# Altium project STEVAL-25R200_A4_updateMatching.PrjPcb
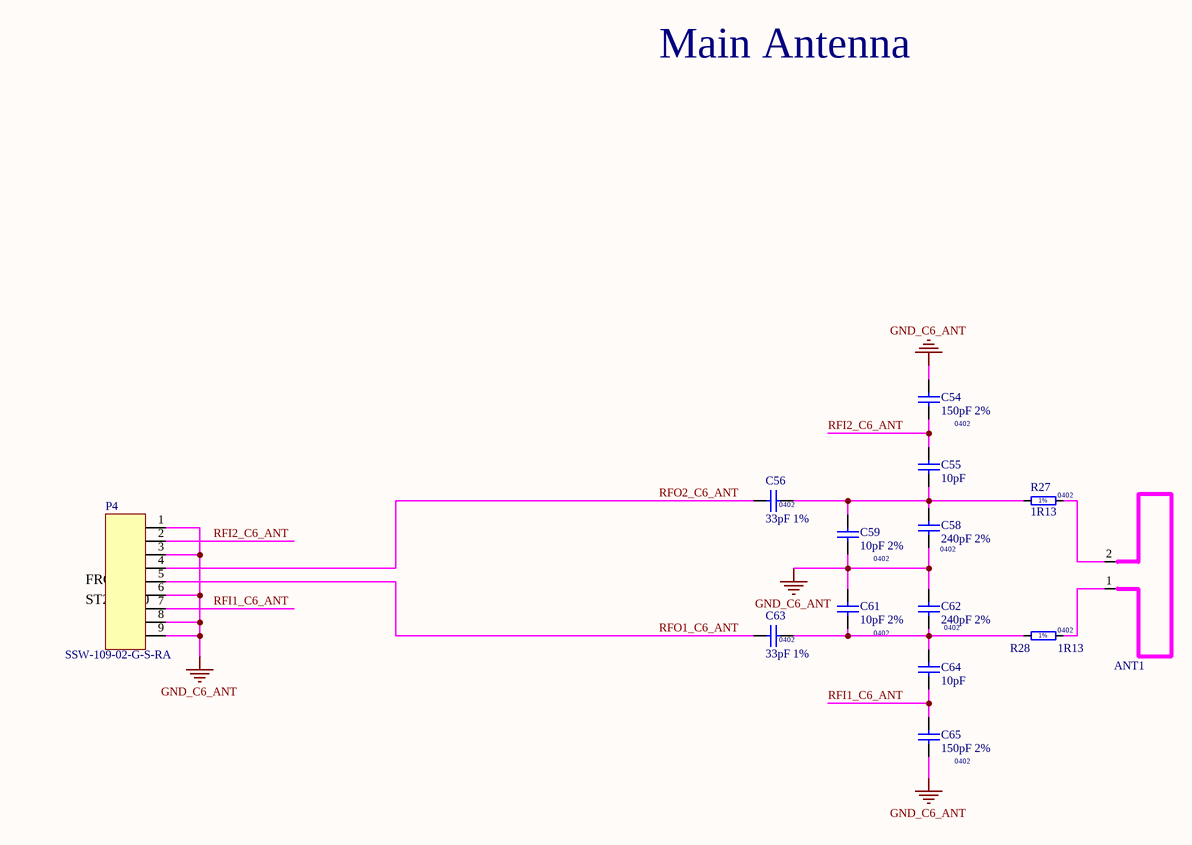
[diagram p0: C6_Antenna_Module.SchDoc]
Company: ST MICROELECTRONICS; date_Dossier: 20 JUNE 2023; Entete_Fichiers_Output: STEVAL-25R200_A2; Reference: /; Revision: A2; Schematics_Reference: /; Schematics_Revision: A2; Schematics_Title: STEVAL-25R200; text_ident_couches: STEVAL-25R200 REV. A2; Title: STEVAL-25R200; Titre_BOM: STEVAL-25R200
7 sheets, 269 parts. Net scope: flat (ports and power ports of the same name join across sheets).
Board file: STEVAL-25R200_A2.PcbDoc
Sheets:
  C6_Antenna_Module.SchDoc
  ST25R200_Module.SchDoc
  STLink_V2.SchDoc
  Hub_And_C7_Antennas.SchDoc
  50_Ohms_Interface.SchDoc
  Flex_Antenna.SchDoc
  Tags.SchDoc

## Sheet C6_Antenna_Module.SchDoc: STEVAL-25R200
size A3; Organization: STMicroelectronics; Address1: SMD Division; Address2: 190, avenue Célestin COQ; Address3: 13106 ROUSSET Cedex; Address4: FRANCE; Revision: A2; SheetNumber: 3; SheetTotal: 7; PageSetup: Record=PageOptions¦CenterHorizontal=True¦CenterVertical=True¦PrintScale=0.71¦XCorrection=1.00¦YCorrection=1.00¦PrintKind=0¦BorderSize=5000000¦LeftOffset=0¦BottomOffset=0¦Orientation=2¦PaperLength=1000¦PaperWidth=1000¦Scale=100¦PaperSource=7¦PrintQuality=-4¦MediaType=1¦DitherType=10¦PaperKind=A4¦PrintScaleMode=1; Reference: /

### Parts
ANT1  ANTENNA-HW-R+T  [ANTENNA-HWR+T]  (value not drawn)  (net tie, no BOM)
C54  150pF 2%  [0402]
C55  10pF  [0402]
C56  33pF 1%  [0402]
C58  240pF 2%  [0402]
C59  10pF 2%  [0402]
C61  10pF 2%  [0402]
C62  240pF 2%  [0402]
C63  33pF 1%  [0402]
C64  10pF  [0402]
C65  150pF 2%  [0402]
P4  SSW-109-02-G-S-RA  [SAMTEC-SSW-1X9PTS-RA-THROUGH-HOLE]
R27  1R13  [0402]
R28  1R13  [0402]

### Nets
GND_C6_ANT: C54.2 C58.1 C59.1 C61.2 C62.2 C65.1 P4.1 P4.3 P4.6 P4.8 P4.9
RFI1_C6_ANT: C64.1 C65.2 P4.7
RFI2_C6_ANT: C54.1 C55.2 P4.2
RFO1_C6_ANT: C63.1 P4.5
RFO2_C6_ANT: C56.1 P4.4
NetANT1_1: ANT1.1 R28.2
NetANT1_2: ANT1.2 R27.2
NetC55_1: C55.1 C56.2 C58.2 C59.2 R27.1
NetC61_1: C61.1 C62.1 C63.2 C64.2 R28.1

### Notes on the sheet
- Main Antenna
- FROM
- ST25R200

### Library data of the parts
ANT1 = ANTENNA-HW-R+T: ANTENNA FOR HW R+T PROJECT; PickPlace: No
C54 C65 = Capacitor 0402 150pF 50V 2% COG: Manufacturer: MULTI-SOURCES; PickPlace: Yes
C55 = Capacitor 0402 10pF 25V 5% NPO: Capacitor 0402 10pF 50V 2% C0G; Manufacturer: MURATA; Manufacturer Part Number: GCM1555C1H100GA16J; PickPlace: Yes
C56 C63 = Capacitor 0402 36pF 50V 2% COG: Capacitor 0402 33pF 50V 1% COG; Manufacturer: MURATA; Manufacturer Part Number: GCM1555C1H330FA16J; PickPlace: Yes
C58 C62 = Capacitor 0402 240pF 50V 2% COG: Manufacturer: MULTI-SOURCES; PickPlace: Yes
C59 = Capacitor 0402 22pF 50V 2% COG: Capacitor 0402 10pF 50V 2% COG; Manufacturer: MURATA; Manufacturer Part Number: GCM1555C1H100GA16J; PickPlace: Yes
C61 = Capacitor 0402 22pF 50V 2% COG: Manufacturer: MURATA; Manufacturer Part Number: GCM1555C1H100GA16J; PickPlace: Yes
C64 = Capacitor 0402 10pF 25V 5% NPO: Capacitor 0402 10pF 50V 2% C0G; Manufacturer: MULTI-SOURCES; PickPlace: Yes
P4 = SSW-109-02-G-S-RA: CONNECTOR SSW-109-02-G-S-RA; Manufacturer: SAMTEC; PickPlace: No
R27 R28 = Resistor 0402 1R13 1%: RESISTOR 0402 1.13 Ohm 1%; Manufacturer: MULTI-SOURCES; PickPlace: Yes

## Sheet ST25R200_Module.SchDoc: STEVAL-25R200
size A3; Organization: STMicroelectronics; Address1: SMD Division; Address2: 190, avenue Célestin COQ; Address3: 13106 ROUSSET Cedex; Address4: FRANCE; Revision: A2; SheetNumber: 2; SheetTotal: 7; PageSetup: Record=PageOptions¦CenterHorizontal=True¦CenterVertical=True¦PrintScale=0.71¦XCorrection=1.00¦YCorrection=1.00¦PrintKind=0¦BorderSize=5000000¦LeftOffset=0¦BottomOffset=0¦Orientation=2¦PaperLength=1000¦PaperWidth=1000¦Scale=100¦PaperSource=7¦PrintQuality=-4¦MediaType=1¦DitherType=10¦PaperKind=A4¦PrintScaleMode=1; Reference: /
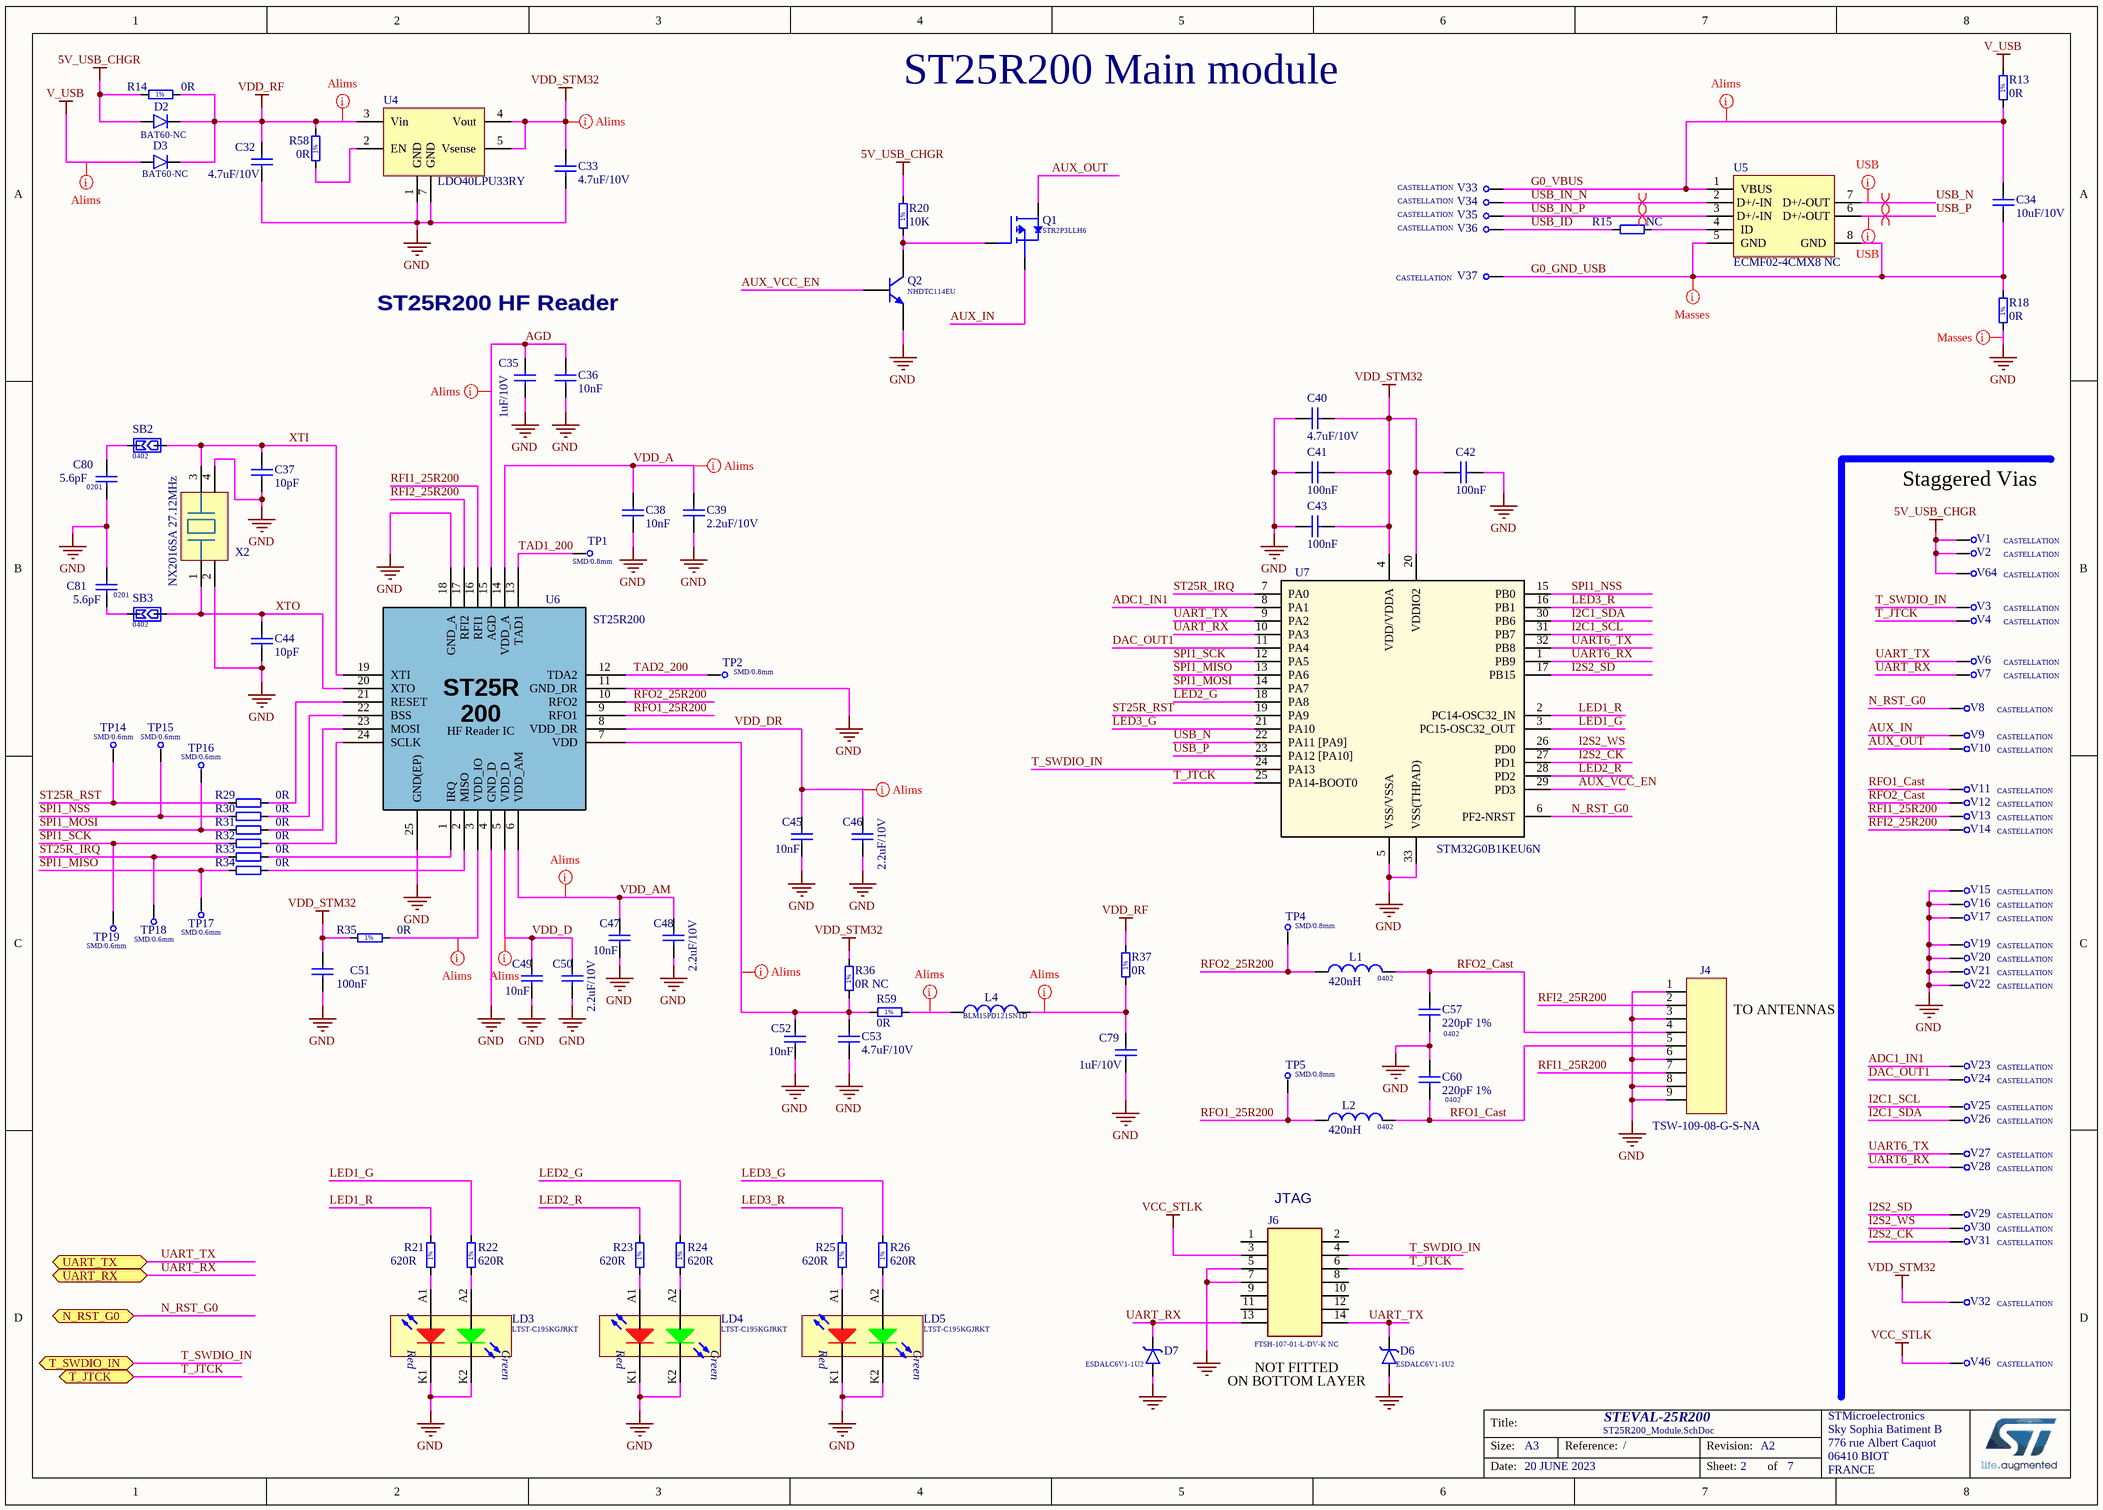
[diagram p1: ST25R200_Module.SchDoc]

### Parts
C32  4.7uF/10V  [0402]
C33  4.7uF/10V  [0402]
C34  10uF/10V  [0402]
C35  1uF/10V  [0201-CAP]
C36  10nF  [0201-CAP]
C37  10pF  [0201-CAP]
C38  10nF  [0201-CAP]
C39  2.2uF/10V  [0201-CAP]
C40  4.7uF/10V  [0402]
C41  100nF  [0201-CAP]
C42  100nF  [0201-CAP]
C43  100nF  [0201-CAP]
C44  10pF  [0201-CAP]
C45  10nF  [0201-CAP]
C46  2.2uF/10V  [0201-CAP]
C47  10nF  [0201-CAP]
C48  2.2uF/10V  [0201-CAP]
C49  10nF  [0201-CAP]
C50  2.2uF/10V  [0201-CAP]
C51  100nF  [0201-CAP]
C52  10nF  [0201-CAP]
C53  4.7uF/10V  [0402]
C57  220pF 1%  [0402]
C60  220pF 1%  [0402]
C79  1uF/10V  [0201-CAP]
C80  5.6pF  Package: 0201  [0201-CAP]
C81  5.6pF  Package: 0201  [0201-CAP]
D2  BAT60-NC  [SOD323]
D3  BAT60-NC  [SOD323]
D6  ESDALC6V1-1U2  [ST-ST0201]
D7  ESDALC6V1-1U2  [ST-ST0201]
J4  TSW-109-08-G-S-NA  [SAMTEC-TSW-1X9PTS-NA-STYLE-08]
J6  FTSH-107-01-L-DV-K NC  [SAMTEC-FTSH-107-01-X-DV-K]
L1  420nH  Package: 0402  [COILCRAFT-SELF-SERIE-0402DF]
L2  420nH  Package: 0402  [COILCRAFT-SELF-SERIE-0402DF]
L4  BLM15PD121SN1D  [0402-SELF]
LD3  LTST-C195KGJRKT  [LITE-ON-SMD-CHIP-LED-TOP-VIEW-BICOLOR-0606]
LD4  LTST-C195KGJRKT  [LITE-ON-SMD-CHIP-LED-TOP-VIEW-BICOLOR-0606]
LD5  LTST-C195KGJRKT  [LITE-ON-SMD-CHIP-LED-TOP-VIEW-BICOLOR-0606]
Q1  STR2P3LLH6  [SOT23-G-D-S]
Q2  NHDTC114EU  [SOT323-BCE]
R13  0R  [0402]
R14  0R  [0402]
R15  NC  [0201-RES]
R18  0R  [0402]
R20  10K  [0402]
R21  620R  [0402]
R22  620R  [0402]
R23  620R  [0402]
R24  620R  [0402]
R25  620R  [0402]
R26  620R  [0402]
R29  0R  [0201-RES]
R30  0R  [0201-RES]
R31  0R  [0201-RES]
R32  0R  [0201-RES]
R33  0R  [0201-RES]
R34  0R  [0201-RES]
R35  0R  [0402]
R36  0R NC  [0402]
R37  0R  [0402]
R58  0R  [0402]
R59  0R  [0402]
SB2  0402  [STRAP-FORMAT-0402-OUVERT]
SB3  0402  [STRAP-FORMAT-0402-OUVERT]
TP1  SMD/0.8mm  [PLAGE-CMS-DIAM-0.8mm]  (no BOM)
TP2  SMD/0.8mm  [PLAGE-CMS-DIAM-0.8mm]  (no BOM)
TP4  SMD/0.8mm  [PLAGE-CMS-DIAM-0.8mm]  (no BOM)
TP5  SMD/0.8mm  [PLAGE-CMS-DIAM-0.8mm]  (no BOM)
TP14  SMD/0.6mm  [PLAGE-CMS-DIAM-0.6mm]  (no BOM)
TP15  SMD/0.6mm  [PLAGE-CMS-DIAM-0.6mm]  (no BOM)
TP16  SMD/0.6mm  [PLAGE-CMS-DIAM-0.6mm]  (no BOM)
TP17  SMD/0.6mm  [PLAGE-CMS-DIAM-0.6mm]  (no BOM)
TP18  SMD/0.6mm  [PLAGE-CMS-DIAM-0.6mm]  (no BOM)
TP19  SMD/0.6mm  [PLAGE-CMS-DIAM-0.6mm]  (no BOM)
U4  LDO40LPU33RY  [ST-DFN6-3x3]
U5  ECMF02-4CMX8 NC  [ST-MICRO-QFN-8L-PKG-2.5x1.2-PAS-0.5]
U6  ST25R200  [ST-QFN24-PAS0.5-4X4-THPAD-2.8MAX]
U7  STM32G0B1KEU6N  [ST-UFQFPN32-PAS-0.5-PKG-5X5X0.55]
V1  CASTELLATION  [CASTELLATED_VIA_Drill=0.6-Pad=1.1]  (no BOM)
V2  CASTELLATION  [CASTELLATED_VIA_Drill=0.6-Pad=1.1]  (no BOM)
V3  CASTELLATION  [CASTELLATED_VIA_Drill=0.6-Pad=1.1]  (no BOM)
V4  CASTELLATION  [CASTELLATED_VIA_Drill=0.6-Pad=1.1]  (no BOM)
V6  CASTELLATION  [CASTELLATED_VIA_Drill=0.6-Pad=1.1]  (no BOM)
V7  CASTELLATION  [CASTELLATED_VIA_Drill=0.6-Pad=1.1]  (no BOM)
V8  CASTELLATION  [CASTELLATED_VIA_Drill=0.6-Pad=1.1]  (no BOM)
V9  CASTELLATION  [CASTELLATED_VIA_Drill=0.6-Pad=1.1]  (no BOM)
V10  CASTELLATION  [CASTELLATED_VIA_Drill=0.6-Pad=1.1]  (no BOM)
V11  CASTELLATION  [CASTELLATED_VIA_Drill=0.6-Pad=1.1]  (no BOM)
V12  CASTELLATION  [CASTELLATED_VIA_Drill=0.6-Pad=1.1]  (no BOM)
V13  CASTELLATION  [CASTELLATED_VIA_Drill=0.6-Pad=1.1]  (no BOM)
V14  CASTELLATION  [CASTELLATED_VIA_Drill=0.6-Pad=1.1]  (no BOM)
V15  CASTELLATION  [CASTELLATED_VIA_Drill=0.6-Pad=1.1]  (no BOM)
V16  CASTELLATION  [CASTELLATED_VIA_Drill=0.6-Pad=1.1]  (no BOM)
V17  CASTELLATION  [CASTELLATED_VIA_Drill=0.6-Pad=1.1]  (no BOM)
V19  CASTELLATION  [CASTELLATED_VIA_Drill=0.6-Pad=1.1]  (no BOM)
V20  CASTELLATION  [CASTELLATED_VIA_Drill=0.6-Pad=1.1]  (no BOM)
V21  CASTELLATION  [CASTELLATED_VIA_Drill=0.6-Pad=1.1]  (no BOM)
V22  CASTELLATION  [CASTELLATED_VIA_Drill=0.6-Pad=1.1]  (no BOM)
V23  CASTELLATION  [CASTELLATED_VIA_Drill=0.6-Pad=1.1]  (no BOM)
V24  CASTELLATION  [CASTELLATED_VIA_Drill=0.6-Pad=1.1]  (no BOM)
V25  CASTELLATION  [CASTELLATED_VIA_Drill=0.6-Pad=1.1]  (no BOM)
V26  CASTELLATION  [CASTELLATED_VIA_Drill=0.6-Pad=1.1]  (no BOM)
V27  CASTELLATION  [CASTELLATED_VIA_Drill=0.6-Pad=1.1]  (no BOM)
V28  CASTELLATION  [CASTELLATED_VIA_Drill=0.6-Pad=1.1]  (no BOM)
V29  CASTELLATION  [CASTELLATED_VIA_Drill=0.6-Pad=1.1]  (no BOM)
V30  CASTELLATION  [CASTELLATED_VIA_Drill=0.6-Pad=1.1]  (no BOM)
V31  CASTELLATION  [CASTELLATED_VIA_Drill=0.6-Pad=1.1]  (no BOM)
V32  CASTELLATION  [CASTELLATED_VIA_Drill=0.6-Pad=1.1]  (no BOM)
V33  CASTELLATION  [CASTELLATED_VIA]  (no BOM)
V34  CASTELLATION  [CASTELLATED_VIA]  (no BOM)
V35  CASTELLATION  [CASTELLATED_VIA]  (no BOM)
V36  CASTELLATION  [CASTELLATED_VIA]  (no BOM)
V37  CASTELLATION  [CASTELLATED_VIA]  (no BOM)
V46  CASTELLATION  [CASTELLATED_VIA_Drill=0.6-Pad=1.1]  (no BOM)
V64  CASTELLATION  [CASTELLATED_VIA_Drill=0.6-Pad=1.1]  (no BOM)
X2  NX2016SA 27.12MHz  [NDK-NX2016SA]

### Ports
N_RST_G0 (bidir), T_JTCK (bidir), T_SWDIO_IN (bidir), UART_RX (bidir), UART_TX (bidir)

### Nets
5V_USB_CHGR: D2.A R14.1 R20.2 V1.1 V2.1 V64.1
GND: C32.1 C33.1 C35.1 C36.1 C37.1 C38.1 C39.1 C40.1 C41.1 C42.2 C43.1 C44.1 C45.1 C46.1 C47.1 C48.1 C49.1 C50.1 C51.1 C52.1 C53.1 C57.1 C60.2 C79.1 C80.1 C81.2 D6.A D7.A J4.1 J4.3 J4.6 J4.8 J4.9 J6.5 J6.7 LD3.K1(RED_cathode) LD3.K2(YellowGreen_cathode) LD4.K1(RED_cathode) LD4.K2(YellowGreen_cathode) LD5.K1(RED_cathode) LD5.K2(YellowGreen_cathode) Q2.E R18.1 U4.1(GND) U4.7(GND) U6.4(GND_D) U6.11(GND_DR) U6.18(GND_A) U6.25(GND(EP)) U7.5(VSS/VSSA) U7.33(VSS(THPAD)) V15.1 V16.1 V17.1 V19.1 V20.1 V21.1 V22.1 X2.2 X2.4
V_USB: D3.A R13.2
VCC_STLK: J6.3 V46.1
VDD_RF: C32.2 D2.K D3.K R14.2 R37.2 R58.2 U4.3(Vin)
VDD_STM32: C33.2 C40.2 C41.2 C42.1 C43.2 C51.2 R35.1 R36.2 U4.4(Vout) U4.5(Vsense) U7.4(VDD/VDDA) U7.20(VDDIO2) V32.1
ADC1_IN1: U7.8(PA1) V23.1
AGD: C35.2 C36.2 U6.15(AGD)
AUX_IN: Q1.S V9.1
AUX_OUT: Q1.D V10.1
AUX_VCC_EN: Q2.B U7.29(PD3)
DAC_OUT1: U7.11(PA4) V24.1
G0_GND_USB: C34.1 R18.2 U5.5(GND) U5.8(GND) V37.1
G0_VBUS: C34.2 R13.1 U5.1(VBUS) V33.1
I2C1_SCL: U7.31(PB7) V25.1
I2C1_SDA: U7.30(PB6) V26.1
I2S2_CK: U7.27(PD1) V31.1
I2S2_SD: U7.17(PB15) V29.1
I2S2_WS: U7.26(PD0) V30.1
LED1_G: R22.2 U7.3(PC15-OSC32_OUT)
LED1_R: R21.2 U7.2(PC14-OSC32_IN)
LED2_G: R24.2 U7.18(PA8)
LED2_R: R23.2 U7.28(PD2)
LED3_G: R26.2 U7.21(PA10)
LED3_R: R25.2 U7.16(PB1)
N_RST_G0: U7.6(PF2-NRST) V8.1 ; port N_RST_G0
RFI1_25R200: J4.7 U6.16(RFI1) V13.1
RFI2_25R200: J4.2 U6.17(RFI2) V14.1
RFO1_25R200: L2.1 TP5.1 U6.9(RFO1)
RFO1_Cast: C60.1 J4.5 L2.2 V11.1
RFO2_25R200: L1.1 TP4.1 U6.10(RFO2)
RFO2_Cast: C57.2 J4.4 L1.2 V12.1
SPI1_MISO: R34.1 TP17.1 U7.13(PA6)
SPI1_MOSI: R31.1 TP16.1 U7.14(PA7)
SPI1_NSS: R30.1 TP15.1 U7.15(PB0)
SPI1_SCK: R32.1 TP19.1 U7.12(PA5)
ST25R_IRQ: R33.1 TP18.1 U7.7(PA0)
ST25R_RST: R29.1 TP14.1 U7.19(PA9)
T_JTCK: J6.6 U7.25(PA14-BOOT0) V4.1 ; port T_JTCK
T_SWDIO_IN: J6.4 U7.24(PA13) V3.1 ; port T_SWDIO_IN
TAD1_200: TP1.1 U6.13(TAD1)
TAD2_200: TP2.1 U6.12(TDA2)
UART6_RX: U7.1(PB9) V28.1
UART6_TX: U7.32(PB8) V27.1
UART_RX: U7.10(PA3) V7.1 ; port UART_RX
UART_TX: D6.K J6.14 U7.9(PA2) V6.1 ; port UART_TX
USB_ID: R15.1 V36.1
USB_IN_N: U5.2(D+/-IN) V34.1
USB_IN_P: U5.3(D+/-IN) V35.1
USB_N: U5.7(D+/-OUT) U7.22(PA11_[PA9])
USB_P: U5.6(D+/-OUT) U7.23(PA12_[PA10])
VDD_A: C38.2 C39.2 U6.14(VDD_A)
VDD_AM: C47.2 C48.2 U6.6(VDD_AM)
VDD_D: C49.2 C50.2 U6.5(VDD_D)
VDD_DR: C45.2 C46.2 U6.8(VDD_DR)
XTI: C37.2 SB2.2 U6.19(XTI) X2.3
XTO: C44.2 SB3.2 U6.20(XTO) X2.1
NetC52_2: C52.2 C53.2 R36.1 R59.1 U6.7(VDD)
NetC79_2: C79.2 L4.2 R37.1
NetC80_2: C80.2 SB2.1
NetC81_1: C81.1 SB3.1
NetD7_K: D7.K J6.13
NetL4_1: L4.1 R59.2
NetLD3_A1: LD3.A1(Red_anode) R21.1
NetLD3_A2: LD3.A2(YellowGreen_anode) R22.1
NetLD4_A1: LD4.A1(Red_anode) R23.1
NetLD4_A2: LD4.A2(YellowGreen_anode) R24.1
NetLD5_A1: LD5.A1(Red_anode) R25.1
NetLD5_A2: LD5.A2(YellowGreen_anode) R26.1
NetQ1_G: Q1.G Q2.C R20.1
NetR15_2: R15.2 U5.4(ID)
NetR29_2: R29.2 U6.21(RESET)
NetR30_2: R30.2 U6.22(BSS)
NetR31_2: R31.2 U6.23(MOSI)
NetR32_2: R32.2 U6.24(SCLK)
NetR33_2: R33.2 U6.1(IRQ)
NetR34_2: R34.2 U6.2(MISO)
NetR35_2: R35.2 U6.3(VDD_IO)
NetR58_1: R58.1 U4.2(EN)

Not connected (* = marked no-connect by the designer): J6 1 2 8 9 10 11 12

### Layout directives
differential pair; net class USB: USB_IN_N, USB_IN_P
net class Alims: AGD, G0_VBUS, NetC52_2, NetC79_2, NetL4_1, NetR35_2, V_USB, VDD_A, VDD_AM, VDD_D, VDD_DR, VDD_RF, VDD_STM32
net class USB: USB_N, USB_P
differential pair: USB_N, USB_P
net class Masses: G0_GND_USB, GND

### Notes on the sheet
- ST25R200 Main module
- ST25R200 HF Reader
- Staggered Vias
- (near J4) TO ANTENNAS
- (near J6) JTAG
- ON BOTTOM LAYER
- (near J6) NOT FITTED
- Labels drawn without touching a wire or pin: UART_RX

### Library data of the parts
C32 C33 C40 C53 = GRM155R61A475MEAA: Cap GRM155R61A475MEAA 4.7uF 10V 0402; Manufacturer: MURATA; PickPlace: Yes
C34 = GRM155R61A106ME44D: Cap GRM155R61A106ME44D 10uF 10V X5R 0402; Manufacturer: MURATA; PickPlace: Yes
C35 C79 = GRM033R61A105ME15: Cap GRM033R61A105ME15 1uF 10V X5R 20% 0201; Manufacturer: MURATA; PickPlace: Yes
C36 C38 C45 C47 C49 C52 = GRM033R61E103KA12D: Cap GRM033R61E103KA12D 10nF 0201; Manufacturer: MURATA; PickPlace: Yes
C37 C44 = Capacitor 0201 10pF 25V: Capacitor 0201 10pF 25V C0G; Manufacturer: MULTI-SOURCES; PickPlace: Yes
C39 C46 C48 C50 = GRM033R61A225ME47: Capacitor GRM033R61A225ME47 2.2uF 10V 0201; Manufacturer: MURATA; PickPlace: Yes
C41-C43 C51 = GRM033C71A104KE14D: Cap GRM033C71A104KE14D 100nF 0201; Manufacturer: MURATA; PickPlace: Yes
C57 C60 = Capacitor 0402 240pF 50V 2% COG: Capacitor 0402 220pF 50V 1% COG; Manufacturer: MURATA; Manufacturer Part Number: GRT1555C1H221FA02D; PickPlace: Yes
C80 C81 = Capacitor 0201 5.6pF 25V C0G: Manufacturer: MULTI-SOURCES; PickPlace: Yes
D2 D3 = BAT60JFILM-NC: DIODE BAT60JFILM NOT FITTED; Manufacturer: ST MICRO; NOT-FITTED: X; PickPlace: Yes
D6 D7 = ESDALC6V1-1U2: ESD PROTECT TRANSIL ESDALC6V1-1U2; Manufacturer: ST MICRO; PickPlace: Yes
J4 = TSW-109-08-G-S-NA: CONNECTOR TSW-109-08-G-S-NA; Manufacturer: SAMTEC; PickPlace: No
J6 = FTSH-107-01-L-DV-K-NC: CONNECTOR FTSH-107-01-L-DV-K NOT FITTED; Manufacturer: SAMTEC; NOT-FITTED: X; PickPlace: Yes
L1 L2 = COILCRAFT-SELF-0402DF-421XJR: Inductor 0402DF-421XJR 420nH; PickPlace: Yes
L4 = BLM15PD121SN1D: SELF BLM15PD121SN1D 0402; Manufacturer: MURATA; PickPlace: Yes
LD3-LD5 = LTST-C195KGJRKT: LED BICOLOR LTST-C195KGJRKT; Manufacturer: LITE ON; PickPlace: Yes
Q1 = STR2P3LLH6: Transistor STR2P3LLH6 SOT23; Manufacturer: ST MICRO; PickPlace: Yes
Q2 = NHDTC114EU: Transistor NHDTC114EU SOT323; Manufacturer: MULTI-SOURCES; PickPlace: Yes
R13 R14 R18 R35 R37 R58 R59 = Resistor 0402 0R: Manufacturer: MULTI-SOURCES; PickPlace: Yes
R15 = Resistor 0201 NOT FITTED: Manufacturer: MULTI-SOURCES; NOT-FITTED: X; PickPlace: Yes
R20 = Resistor 0402 10K 1%: Manufacturer: MULTI-SOURCES; PickPlace: Yes
R21-R26 = Resistor 0402 620R 1%: Manufacturer: MULTI-SOURCES; PickPlace: Yes
R29-R34 = Resistor 0201 0R: Manufacturer: MULTI-SOURCES; PickPlace: Yes
R36 = Resistor 0402 0R NC: Resistor 0402 0R NOT FITTED; Manufacturer: MULTI-SOURCES; NOT-FITTED: X; PickPlace: Yes
SB2 SB3 = STRAP-0402-OUVERT: SOLDER BRIDGE OPEN SIZE 0402; PickPlace: No
TP1 TP2 TP4 TP5 = PLAGE-CMS-DIAM-0.8mm: SMD PAD DIAM. 0.8mm; PickPlace: No
TP14-TP19 = PLAGE-CMS-DIAM-0.6mm: SMD PAD DIAM. 0.6mm; PickPlace: No
U4 = LDO40LPU33RY: LDO LDO40LPU33RY DFN6; Manufacturer: ST MICRO; PickPlace: Yes
U5 = ECMF02-4CMX8-NC: ESD PROTECTION ECMF02-4CMX8 NOT FITTED; Manufacturer: ST MICRO; NOT-FITTED: X; PickPlace: Yes
U6 = ST25R200: HF READER ST25R200 QFN24; Manufacturer: ST MICRO; PickPlace: Yes; Note: Fourni par client
U7 = STM32G0B1KEU6N: MCU STM32G0B1KEU6N UFQFPN32; Manufacturer: ST MICRO; PickPlace: Yes
V1-V4 V6-V17 V19-V32 V46 V64 = CASTELLATED_VIA_Drill=0.6-Pad=1.1: CASTELLATED VIA Drill=0.6 Pad=1.1; NOT-FITTED: X; PickPlace: No
V33-V37 = CASTELLATED_VIA: NOT-FITTED: X; PickPlace: No
X2 = NDK-NX2016SA-27.12MHZ-EXS00A-CS01188: CRYSTAL NX2016SA-27.12MHZ-EXS00A-CS01188 NDK; PickPlace: Yes

## Sheet STLink_V2.SchDoc: STEVAL-25R200
size A3; Organization: STMicroelectronics; Address1: SMD Division; Address2: 190, avenue Célestin COQ; Address3: 13106 ROUSSET Cedex; Address4: FRANCE; Revision: A2; SheetNumber: 1; SheetTotal: 7; PageSetup: Record=PageOptions¦CenterHorizontal=True¦CenterVertical=True¦PrintScale=0.71¦XCorrection=1.00¦YCorrection=1.00¦PrintKind=0¦BorderSize=5000000¦LeftOffset=0¦BottomOffset=0¦Orientation=2¦PaperLength=1000¦PaperWidth=1000¦Scale=100¦PaperSource=7¦PrintQuality=-4¦MediaType=1¦DitherType=10¦PaperKind=A4¦PrintScaleMode=1; Reference: /
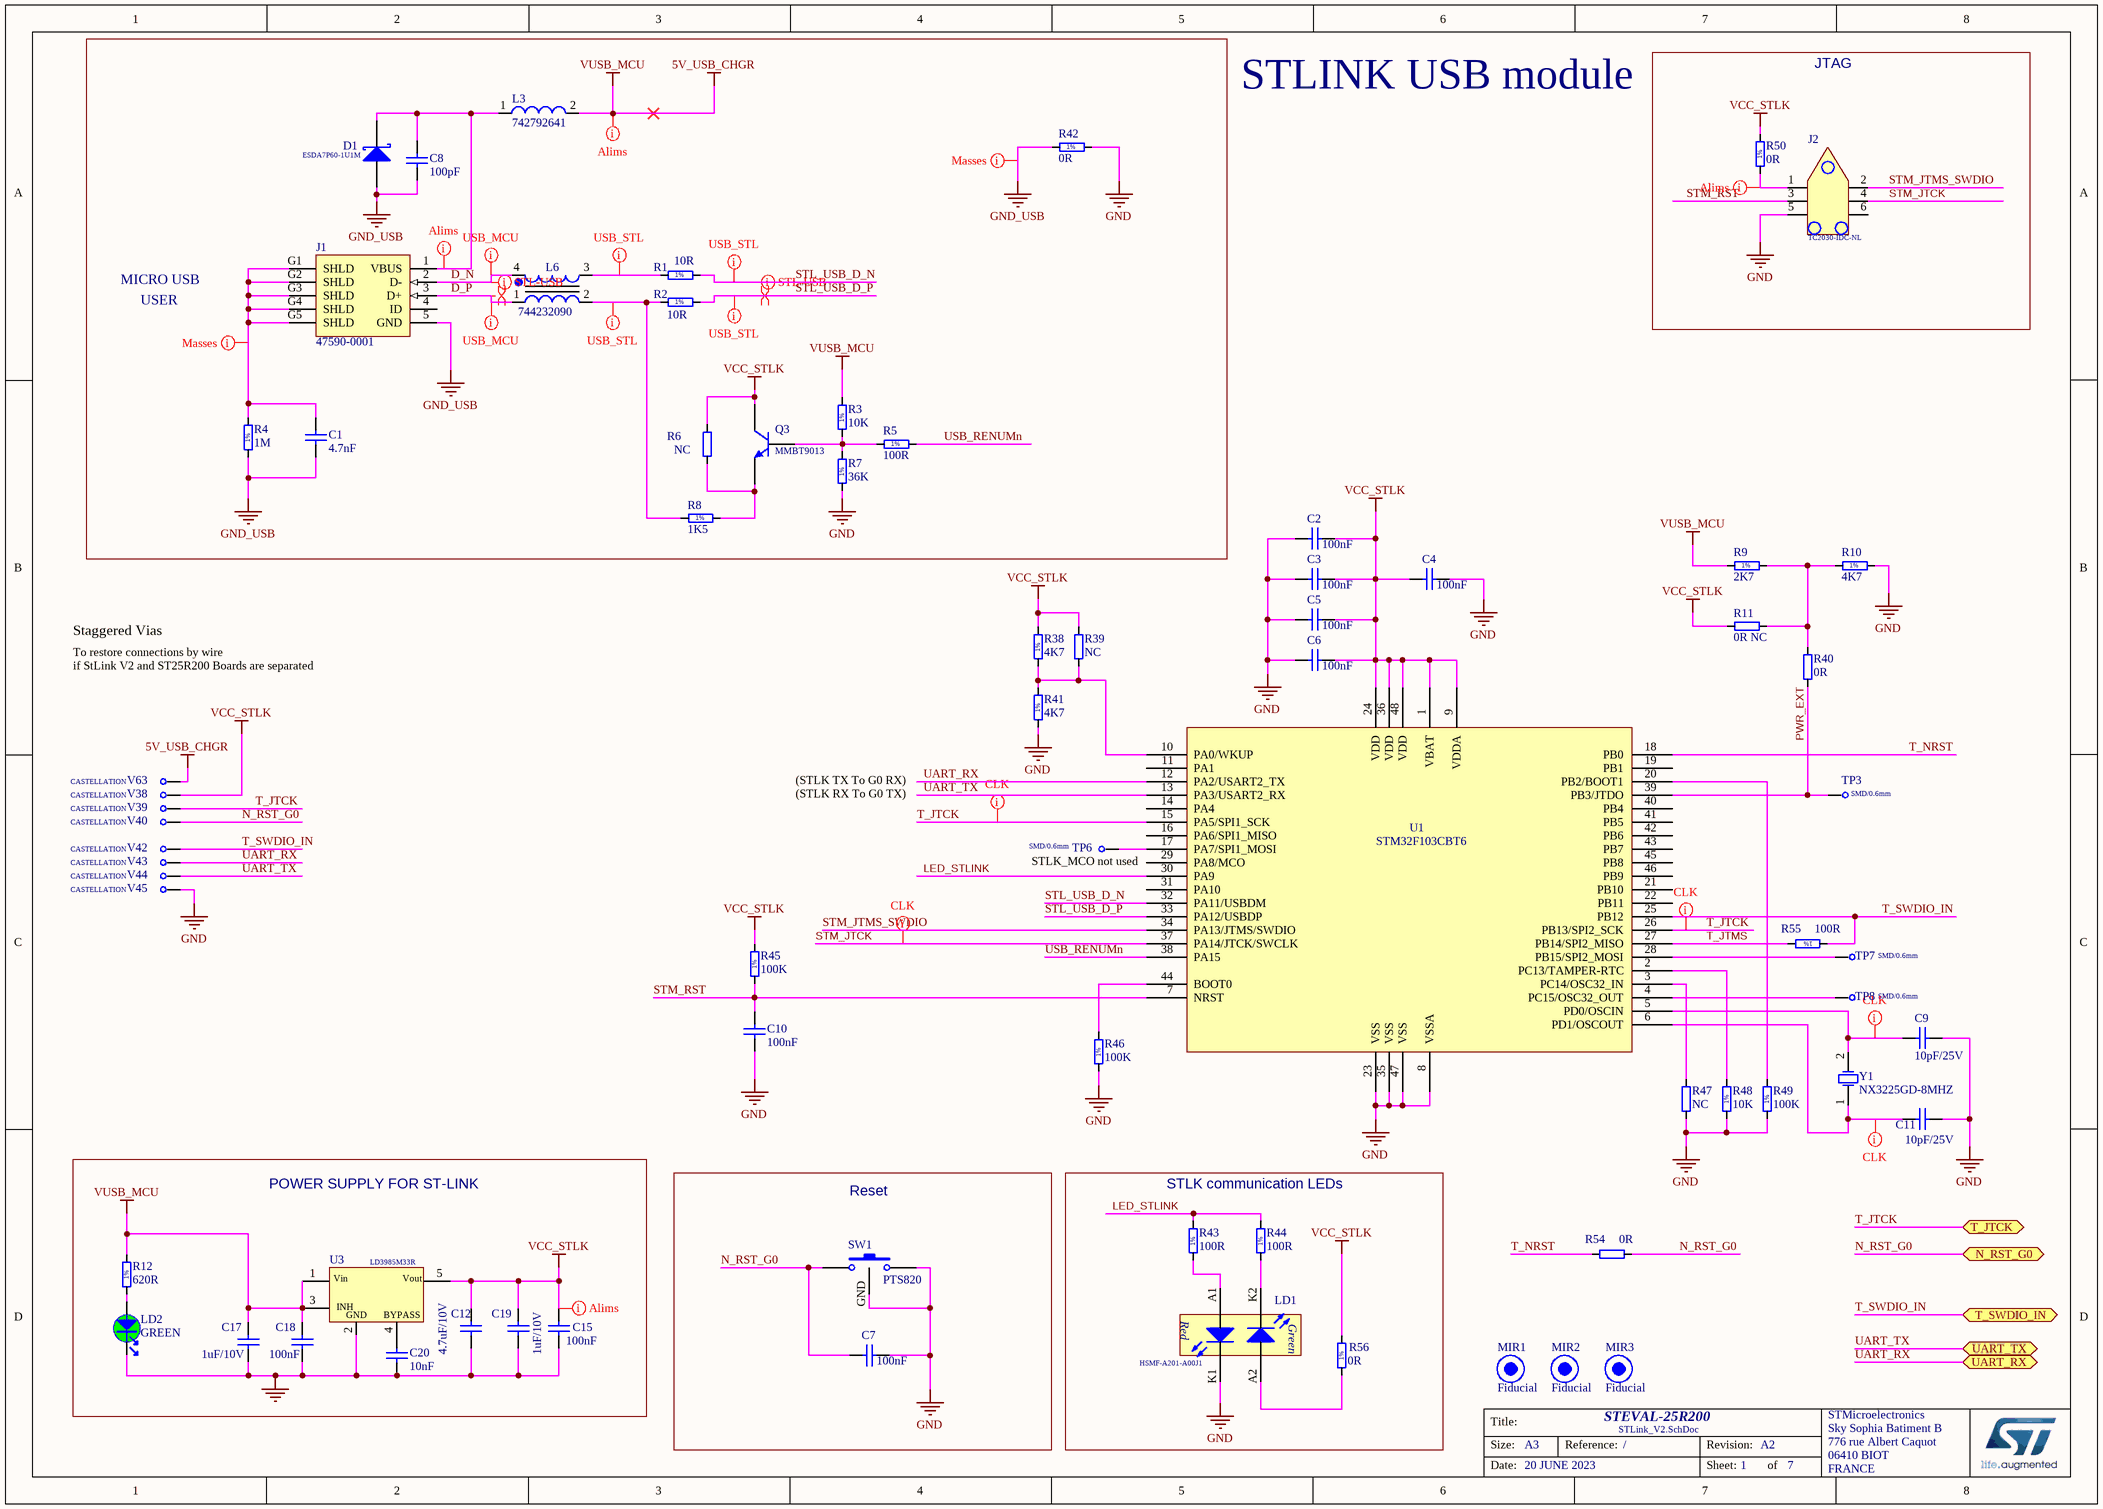
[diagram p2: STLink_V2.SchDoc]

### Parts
C1  4.7nF  [0402]
C2  100nF  [0201-CAP]
C3  100nF  [0201-CAP]
C4  100nF  [0201-CAP]
C5  100nF  [0201-CAP]
C6  100nF  [0201-CAP]
C7  100nF  [0201-CAP]
C8  100pF  [0402]
C9  10pF/25V  [0201-CAP]
C10  100nF  [0201-CAP]
C11  10pF/25V  [0201-CAP]
C12  4.7uF/10V  [0402]
C15  100nF  [0201-CAP]
C17  1uF/10V  [0201-CAP]
C18  100nF  [0201-CAP]
C19  1uF/10V  [0201-CAP]
C20  10nF  [0201-CAP]
D1  ESDA7P60-1U1M  [ST-PACKAGE-1610-2PINS-A-K]
J1  47590-0001  [MOLEX-47590-0001]
J2  TC2030-IDC-NL  [TAG-CONNECT-FOOTPRINT-TC2030-IDC-NL]  (no BOM)
L3  742792641  [0603]
L6  744232090  [WURTH-WE-CNSW-1206]
LD1  HSMF-A201-A00J1  [LED-PACKAGE-PLCC-4]
LD2  GREEN  [EVERLIGHT-19-213]
MIR1  Fiducial  [mire_optique_standard]  (no BOM)
MIR2  Fiducial  [mire_optique_standard]  (no BOM)
MIR3  Fiducial  [mire_optique_standard]  (no BOM)
Q3  MMBT9013  [SOT23-B-C-E]
R1  10R  [0402]
R2  10R  [0402]
R3  10K  [0201-RES]
R4  1M  [0402]
R5  100R  [0201-RES]
R6  NC  [0201-RES]
R7  36K  [0201-RES]
R8  1K5  [0201-RES]
R9  2K7  [0201-RES]
R10  4K7  [0201-RES]
R11  0R NC  [0201-RES]
R12  620R  [0402]
R38  4K7  [0201-RES]
R39  NC  [0201-RES]
R40  0R  [0201-RES]
R41  4K7  [0201-RES]
R42  0R  [0402]
R43  100R  [0402]
R44  100R  [0402]
R45  100K  [0201-RES]
R46  100K  [0201-RES]
R47  NC  [0201-RES]
R48  10K  [0201-RES]
R49  100K  [0201-RES]
R50  0R  [0402]
R54  0R  [0201-RES]
R55  100R  [0201-RES]
R56  0R  [0402]
SW1  PTS820  [C&K-INTER-SERIE-PTS820-WITHOUT-PEGS-H=2.0]
TP3  SMD/0.6mm  [PLAGE-CMS-DIAM-0.6mm]  (no BOM)
TP6  SMD/0.6mm  [PLAGE-CMS-DIAM-0.6mm]  (no BOM)
TP7  SMD/0.6mm  [PLAGE-CMS-DIAM-0.6mm]  (no BOM)
TP8  SMD/0.6mm  [PLAGE-CMS-DIAM-0.6mm]  (no BOM)
U1  STM32F103CBT6  [ST-LQFP48-PAS-0.5-7x7-h=1.6]
U3  LD3985M33R  [SOT23-5PINS]
V38  CASTELLATION  [CASTELLATED_VIA_Drill=0.6-Pad=1.1]  (no BOM)
V39  CASTELLATION  [CASTELLATED_VIA_Drill=0.6-Pad=1.1]  (no BOM)
V40  CASTELLATION  [CASTELLATED_VIA_Drill=0.6-Pad=1.1]  (no BOM)
V42  CASTELLATION  [CASTELLATED_VIA_Drill=0.6-Pad=1.1]  (no BOM)
V43  CASTELLATION  [CASTELLATED_VIA_Drill=0.6-Pad=1.1]  (no BOM)
V44  CASTELLATION  [CASTELLATED_VIA_Drill=0.6-Pad=1.1]  (no BOM)
V45  CASTELLATION  [CASTELLATED_VIA_Drill=0.6-Pad=1.1]  (no BOM)
V63  CASTELLATION  [CASTELLATED_VIA_Drill=0.6-Pad=1.1]  (no BOM)
Y1  NX3225GD-8MHZ  [NDK-NX3225GD]

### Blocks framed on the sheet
JTAG: J2 R50
POWER SUPPLY FOR ST-LINK: C12 C15 C17-C20 LD2 R12 U3
Reset: C7 SW1
STLK communication LEDs: LD1 R43 R44 R56

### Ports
N_RST_G0 (bidir), T_JTCK (bidir), T_SWDIO_IN (bidir), UART_RX (bidir), UART_TX (bidir)

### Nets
5V_USB_CHGR: C17.2 C18.2 L3.2 R3.2 R9.1 R12.2 U3.1(Vin) U3.3(CE) V63.1  [also labelled VUSB_MCU]
GND: C2.2 C3.2 C4.1 C5.2 C6.2 C7.1 C9.2 C10.2 C11.2 C12.1 C15.1 C17.1 C18.1 C19.1 C20.1 J2.5 LD1.K1(RED_cathode) LD2.K R7.1 R10.2 R41.1 R42.2 R46.1 R47.1 R48.1 R49.1 SW1.2 SW1.GND U1.8(VSSA) U1.23(VSS) U1.35(VSS) U1.47(VSS) U3.2(GND) V45.1
GND_USB: C1.1 C8.1 D1.A J1.5(GND) R4.1 R42.1
VCC_STLK: C2.1 C3.1 C4.2 C5.1 C6.1 C12.2 C15.2 C19.2 Q3.C R6.2 R11.1 R38.2 R39.2 R45.2 R50.2 R56.2 U1.1(VBAT) U1.9(VDDA) U1.24(VDD) U1.36(VDD) U1.48(VDD) U3.5(Vout) V38.1
D_N: J1.2(D-) L6.4
D_P: J1.3(D+) L6.1
LED_STLINK: R43.2 R44.2 U1.30(PA9)
N_RST_G0: C7.2 R54.1 SW1.1 V40.1 ; port N_RST_G0
PWR_EXT: R40.1 TP3.1 U1.39(PB3/JTDO)
STL_USB_D_N: R1.2 U1.32(PA11/USBDM)
STL_USB_D_P: R2.2 U1.33(PA12/USBDP)
STM_JTCK: J2.4 U1.37(PA14/JTCK/SWCLK)
STM_JTMS_SWDIO: J2.2 U1.34(PA13/JTMS/SWDIO)
STM_RST: C10.1 J2.3 R45.1 U1.7(NRST)
T_JTCK: U1.15(PA5/SPI1_SCK) U1.26(PB13/SPI2_SCK) V39.1 ; port T_JTCK
T_JTMS: R55.2 U1.27(PB14/SPI2_MISO)
T_NRST: R54.2 U1.18(PB0)
T_SWDIO_IN: R55.1 U1.25(PB12) V42.1 ; port T_SWDIO_IN
UART_RX: U1.12(PA2/USART2_TX) V43.1 ; port UART_RX
UART_TX: U1.13(PA3/USART2_RX) V44.1 ; port UART_TX
USB_RENUMn: R5.2 U1.38(PA15)
NetC1_2: C1.2 J1.G1(SHLD) J1.G2(SHLD) J1.G3(SHLD) J1.G4(SHLD) J1.G5(SHLD) R4.2
NetC8_2: C8.2 D1.K J1.1(VBUS) L3.1
NetC9_1: C9.1 U1.5(PD0/OSCIN) Y1.2(OSC2)
NetC11_1: C11.1 U1.6(PD1/OSCOUT) Y1.1(OSC1)
NetC20_2: C20.2 U3.4(BYPASS)
NetJ2_1: J2.1 R50.1
NetL6_2: L6.2 R2.1 R8.1
NetL6_3: L6.3 R1.1
NetLD1_A1: LD1.A1(Red_anode) R43.1
NetLD1_A2: LD1.A2(YellowGreen_anode) R56.1
NetLD1_K2: LD1.K2(YellowGreen_cathode) R44.1
NetLD2_A: LD2.A R12.1
NetQ3_B: Q3.B R3.1 R5.1 R7.2
NetQ3_E: Q3.E R6.1 R8.2
NetR9_2: R9.2 R10.1 R11.2 R40.2
NetR38_1: R38.1 R39.1 R41.2 U1.10(PA0/WKUP)
NetR46_2: R46.2 U1.44(BOOT0)
NetR47_2: R47.2 U1.3(PC14/OSC32_IN)
NetR48_2: R48.2 U1.2(PC13/TAMPER-RTC)
NetR49_2: R49.2 U1.20(PB2/BOOT1)
NetTP6_1: TP6.1 U1.17(PA7/SPI1_MOSI)
NetTP7_1: TP7.1 U1.28(PB15/SPI2_MOSI)
NetTP8_1: TP8.1 U1.4(PC15/OSC32_OUT)

Not connected (* = marked no-connect by the designer): J1 4(ID); J2 6; U1 11(PA1) 14(PA4) 16(PA6/SPI1_MISO) 19(PB1) 21(PB10) 22(PB11) 29(PA8/MCO) 31(PA10) 40(PB4) 41(PB5) 42(PB6) 43(PB7) 45(PB8) 46(PB9)

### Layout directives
net class CLK: NetC9_1, NetC11_1, STM_JTCK, T_JTCK
net class Alims: 5V_USB_CHGR, NetC8_2, NetJ2_1, VCC_STLK
net class USB_MCU: D_N, D_P
net class USB_STL: NetL6_2, NetL6_3, STL_USB_D_N, STL_USB_D_P
differential pair: D_N, D_P, STL_USB_D_N, STL_USB_D_P
net class Masses: GND_USB, NetC1_2

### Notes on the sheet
- STLINK USB module
- MICRO USB
- USER
- Staggered Vias
- To restore connections by wire
- if StLink V2 and ST25R200 Boards are separated
- (STLK TX To G0 RX)
- (STLK RX To G0 TX)
- (near TP6) STLK_MCO not used

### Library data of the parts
C1 = Capacitor 0402 4.7nF 25V 10% X7R: Manufacturer: MULTI-SOURCES; PickPlace: Yes
C2-C7 C10 C15 C18 = GRM033C71A104KE14D: as C41 on sheet ST25R200_Module
C8 = Capacitor 0402 100pF 50V 5% COG: Manufacturer: MULTI-SOURCES; PickPlace: Yes
C9 C11 = Capacitor 0201 10pF 25V: as C37 on sheet ST25R200_Module
C12 = GRM155R61A475MEAA: as C32 on sheet ST25R200_Module
C17 C19 = GRM033R61A105ME15: as C35 on sheet ST25R200_Module
C20 = GRM033R61E103KA12D: as C36 on sheet ST25R200_Module
D1 = ESDA7P60-1U1M: Voltage suppressor ESDA7P60-1U1M; Manufacturer: STMicroelectronics; PickPlace: Yes
J1 = 47590-0001: 47590-0001 - MICRO USB AB; Manufacturer: MOLEX; PickPlace: Yes
J2 = TAG-CONNECT-FOOTPRINT-FOR-TC2030-IDC-NL: FOOTPRINT FOR TC2030-IDC-NL; Manufacturer: TAG Connect; PickPlace: No
L3 = WURTH-742792641: 742792641 EMI FERRITE BEAD 300 Ohms; Manufacturer: WURTH; PickPlace: Yes
L6 = WURTH-744232090: 744232090 COMMON MODE FILTER; Manufacturer: WURTH; PickPlace: Yes
LD1 = HSMF-A201-A00J1: LED BICOLOR HSMF-A201-A00J1; Manufacturer: BROADCOM; PickPlace: Yes
LD2 = 19-213SYGC/S530-E2/TR8: GREEN LED 19-213SYGC/S530-E2/TR8; Manufacturer: EVERLIGHT; PickPlace: Yes
MIR1-MIR3 = Mire-Optique: Fiducial for SMD Components; PickPlace: Yes
Q3 = MMBT9013L-G-AE3: Transistor MMBT9013L-G-AE3 NPN; Manufacturer: UNISONIC TECH.; PickPlace: Yes
R1 R2 = Resistor 0402 10R 1%: Manufacturer: MULTI-SOURCES; PickPlace: Yes
R3 R48 = Resistor 0201 10K 1%: Manufacturer: MULTI-SOURCES; PickPlace: Yes
R4 = Resistor 0402 1M 1%: Manufacturer: MULTI-SOURCES; PickPlace: Yes
R5 R55 = Resistor 0201 100R 1%: Manufacturer: MULTI-SOURCES; PickPlace: Yes
R6 R39 R47 = Resistor 0201 NOT FITTED: as R15 on sheet ST25R200_Module
R7 = Resistor 0201 36K 1%: Manufacturer: MULTI-SOURCES; PickPlace: Yes
R8 = Resistor 0201 1K5 1%: Manufacturer: MULTI-SOURCES; PickPlace: Yes
R9 = Resistor 0201 2K7 1%: Manufacturer: MULTI-SOURCES; PickPlace: Yes
R10 R38 R41 = Resistor 0201 4K7 1%: Manufacturer: MULTI-SOURCES; PickPlace: Yes
R11 = Resistor 0201 0R NC: RESISTOR 0201 0R NOT FITTED; Manufacturer: MULTI-SOURCES; NOT-FITTED: X; PickPlace: Yes
R12 = Resistor 0402 620R 1%: as R21 on sheet ST25R200_Module
R40 R54 = Resistor 0201 0R: as R29 on sheet ST25R200_Module
R42 R50 R56 = Resistor 0402 0R: as R13 on sheet ST25R200_Module
R43 R44 = Resistor 0402 100R 1%: Manufacturer: MULTI-SOURCES; PickPlace: Yes
R45 R46 R49 = Resistor 0201 100K 1%: Manufacturer: MULTI-SOURCES; PickPlace: Yes
SW1 = PTS820-J20M-SMTR-LFS: PUSH BUTTON PTS820-J20M-SMTR-LFS; Manufacturer: C&K; PickPlace: Yes
TP3 TP6-TP8 = PLAGE-CMS-DIAM-0.6mm: SMD PAD DIAM. 0.6mm; PickPlace: No
U1 = STM32F103CBT6: IC STM32F103CBT6 LQFP48; Manufacturer: ST MICRO; PickPlace: Yes
U3 = LD3985M33R: LDO LD3985M33R SOT23-5; Manufacturer: STMicroelectronics; PickPlace: Yes
V38-V40 V42-V45 V63 = CASTELLATED_VIA_Drill=0.6-Pad=1.1: as V1 on sheet ST25R200_Module
Y1 = NX3225GD-8MHZ-EXS00A-CG04874: SMD CRYSTAL NX3225GD-8MHZ-EXS00A-CG04874; Manufacturer: NDK; PickPlace: Yes

## Sheet Hub_And_C7_Antennas.SchDoc: STEVAL-25R200
size A3; Organization: STMicroelectronics; Address1: SMD Division; Address2: 190, avenue Célestin COQ; Address3: 13106 ROUSSET Cedex; Address4: FRANCE; Revision: A2; SheetNumber: 4; SheetTotal: 7; PageSetup: Record=PageOptions¦CenterHorizontal=True¦CenterVertical=True¦PrintScale=0.71¦XCorrection=1.00¦YCorrection=1.00¦PrintKind=0¦BorderSize=5000000¦LeftOffset=0¦BottomOffset=0¦Orientation=2¦PaperLength=1000¦PaperWidth=1000¦Scale=100¦PaperSource=7¦PrintQuality=-4¦MediaType=1¦DitherType=10¦PaperKind=A4¦PrintScaleMode=1; Reference: /
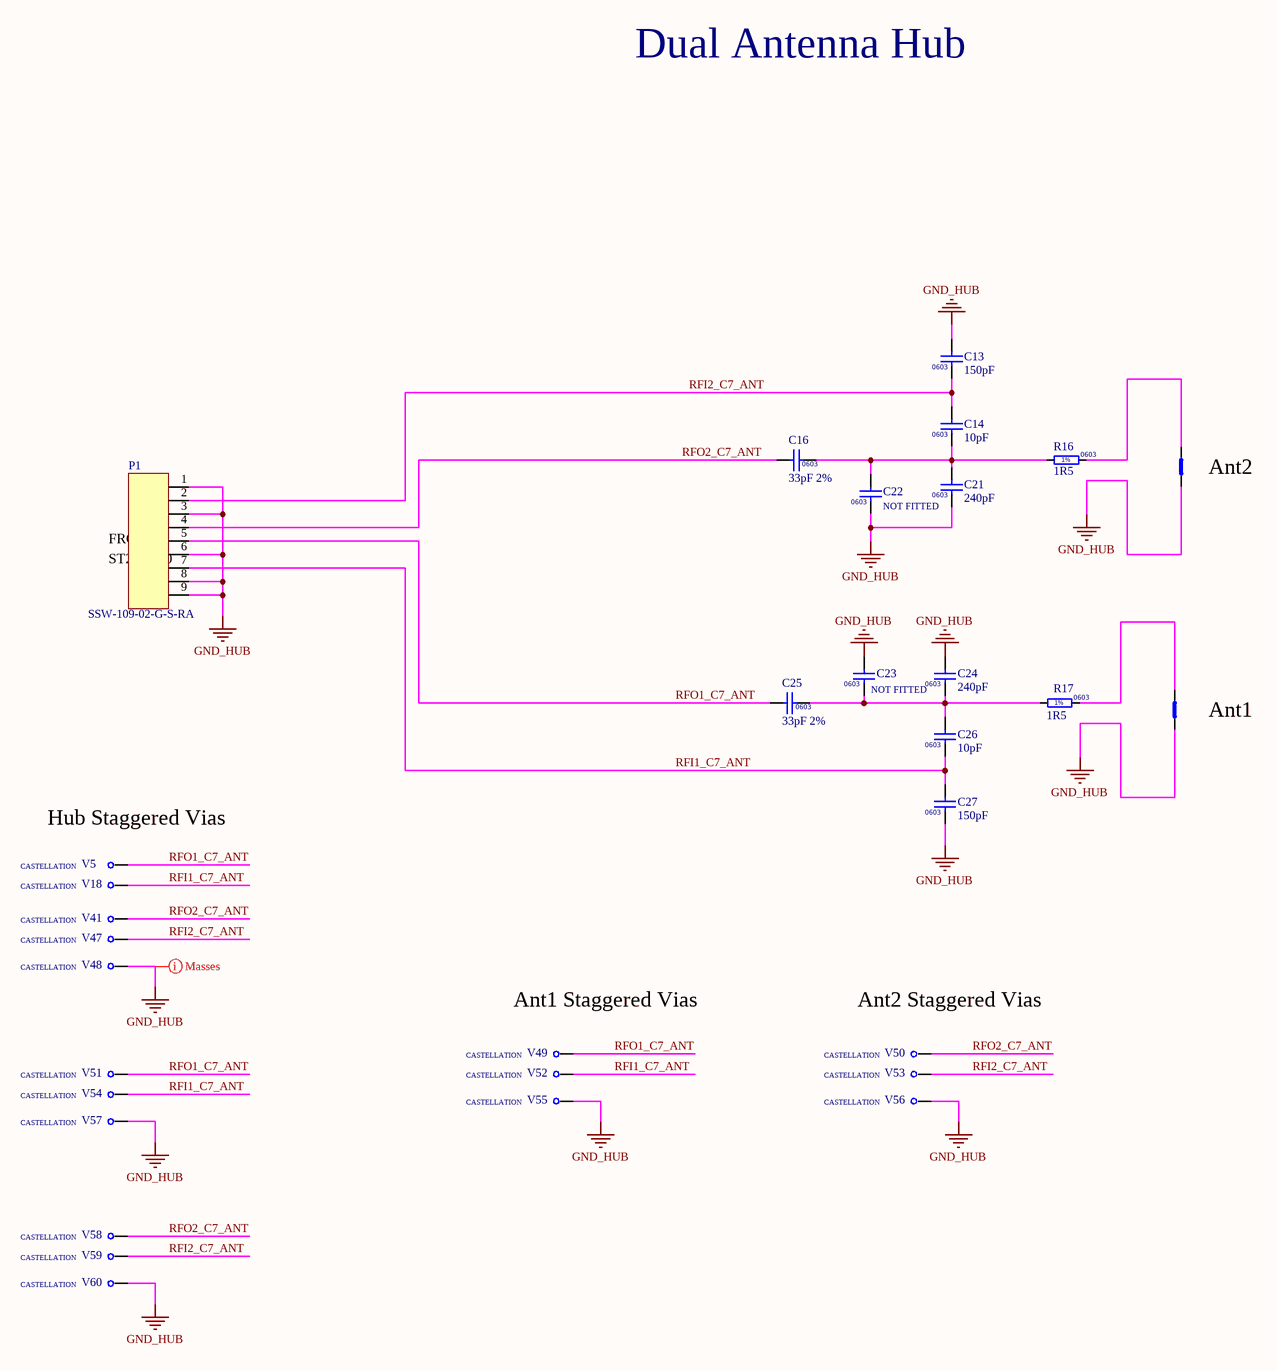
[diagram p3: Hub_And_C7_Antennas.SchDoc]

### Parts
C13  150pF  [0603]
C14  10pF  [0603]
C16  33pF 2%  [0603]
C21  240pF  [0603]
C22  NOT FITTED  [0603]
C23  NOT FITTED  [0603]
C24  240pF  [0603]
C25  33pF 2%  [0603]
C26  10pF  [0603]
C27  150pF  [0603]
NT_C7_1  Net-Tie-Width-0.50mm  [Net-Tie-WIDTH-0.50mm]  (value not drawn)  (net tie, no BOM)
NT_C7_2  Net-Tie-Width-0.50mm  [Net-Tie-WIDTH-0.50mm]  (value not drawn)  (net tie, no BOM)
P1  SSW-109-02-G-S-RA  [SAMTEC-SSW-1X9PTS-RA-THROUGH-HOLE]
R16  1R5  [0603]
R17  1R5  [0603]
V5  CASTELLATION  [CASTELLATED_VIA]  (no BOM)
V18  CASTELLATION  [CASTELLATED_VIA]  (no BOM)
V41  CASTELLATION  [CASTELLATED_VIA]  (no BOM)
V47  CASTELLATION  [CASTELLATED_VIA]  (no BOM)
V48  CASTELLATION  [CASTELLATED_VIA]  (no BOM)
V49  CASTELLATION  [CASTELLATED_VIA]  (no BOM)
V50  CASTELLATION  [CASTELLATED_VIA]  (no BOM)
V51  CASTELLATION  [CASTELLATED_VIA]  (no BOM)
V52  CASTELLATION  [CASTELLATED_VIA]  (no BOM)
V53  CASTELLATION  [CASTELLATED_VIA]  (no BOM)
V54  CASTELLATION  [CASTELLATED_VIA]  (no BOM)
V55  CASTELLATION  [CASTELLATED_VIA]  (no BOM)
V56  CASTELLATION  [CASTELLATED_VIA]  (no BOM)
V57  CASTELLATION  [CASTELLATED_VIA]  (no BOM)
V58  CASTELLATION  [CASTELLATED_VIA]  (no BOM)
V59  CASTELLATION  [CASTELLATED_VIA]  (no BOM)
V60  CASTELLATION  [CASTELLATED_VIA]  (no BOM)

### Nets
GND_HUB: C13.2 C21.1 C22.1 C23.2 C24.2 C27.1 NT_C7_1.1 NT_C7_2.1 P1.1 P1.3 P1.6 P1.8 P1.9 V48.1 V55.1 V56.1 V57.1 V60.1
RFI1_C7_ANT: C26.1 C27.2 P1.7 V18.1 V52.1 V54.1
RFI2_C7_ANT: C13.1 C14.2 P1.2 V47.1 V53.1 V59.1
RFO1_C7_ANT: C25.1 P1.5 V5.1 V49.1 V51.1
RFO2_C7_ANT: C16.1 P1.4 V41.1 V50.1 V58.1
NetC14_1: C14.1 C16.2 C21.2 C22.2 R16.1
NetC23_1: C23.1 C24.1 C25.2 C26.2 R17.1
NetNT_C7_1_2: NT_C7_1.2 R17.2
NetNT_C7_2_2: NT_C7_2.2 R16.2

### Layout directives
net class Masses: GND_HUB

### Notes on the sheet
- Dual Antenna Hub
- (near NT_C7_2) Ant2
- FROM
- ST25R200
- (near NT_C7_1) Ant1
- Hub Staggered Vias
- Ant1 Staggered Vias
- Ant2 Staggered Vias

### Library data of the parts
C13 C27 = Capacitor 0603 150pF 50V 2% COG: Manufacturer: MULTI-SOURCES; PickPlace: Yes
C14 C26 = Capacitor 0603 10pF 25V 5% C0G: Manufacturer: MULTI-SOURCES; PickPlace: Yes
C16 C25 = Capacitor 0603 39pF 50V 2% COG: Capacitor 0603 33pF 50V 2% COG; Manufacturer: MURATA; NOT-FITTED: GCM1885C1H330GA16D; PickPlace: Yes
C21 = Capacitor 0603 220pF 50V C0G 2%: Capacitor 0603 240pF 50V C0G 2%; Manufacturer: MURATA; NOT-FITTED: GRM1885C1H241GA01J; PickPlace: Yes
C22 C23 = Capacitor 0603 18pF 50V 2% COG: Manufacturer: MULTI-SOURCES; PickPlace: Yes
C24 = Capacitor 0603 220pF 50V C0G 2%: Capacitor 0603 240pF 50V C0G 2%; Manufacturer: MURATA; Manufacturer Part Number: GRM1885C1H241GA01J; PickPlace: Yes
NT_C7_1 NT_C7_2 = Net-Tie-Width-0.50mm: Net Tie Width 0.50mm; PickPlace: No
P1 = SSW-109-02-G-S-RA: as P4 on sheet C6_Antenna_Module
R16 R17 = Resistor 0603 1R5 1%: RESISTOR 0603 1.5 Ohm 1%; Manufacturer: MULTI-SOURCES; PickPlace: Yes
V5 V18 V41 V47-V60 = CASTELLATED_VIA: NOT-FITTED: X; PickPlace: No

## Sheet 50_Ohms_Interface.SchDoc: STEVAL-25R200
size A3; Organization: STMicroelectronics; Address1: SMD Division; Address2: 190, avenue Célestin COQ; Address3: 13106 ROUSSET Cedex; Address4: FRANCE; Revision: A2; SheetNumber: 6; SheetTotal: 7; PageSetup: Record=PageOptions¦CenterHorizontal=True¦CenterVertical=True¦PrintScale=0.71¦XCorrection=1.00¦YCorrection=1.00¦PrintKind=0¦BorderSize=5000000¦LeftOffset=0¦BottomOffset=0¦Orientation=2¦PaperLength=1000¦PaperWidth=1000¦Scale=100¦PaperSource=7¦PrintQuality=-4¦MediaType=1¦DitherType=10¦PaperKind=A4¦PrintScaleMode=1; Reference: /
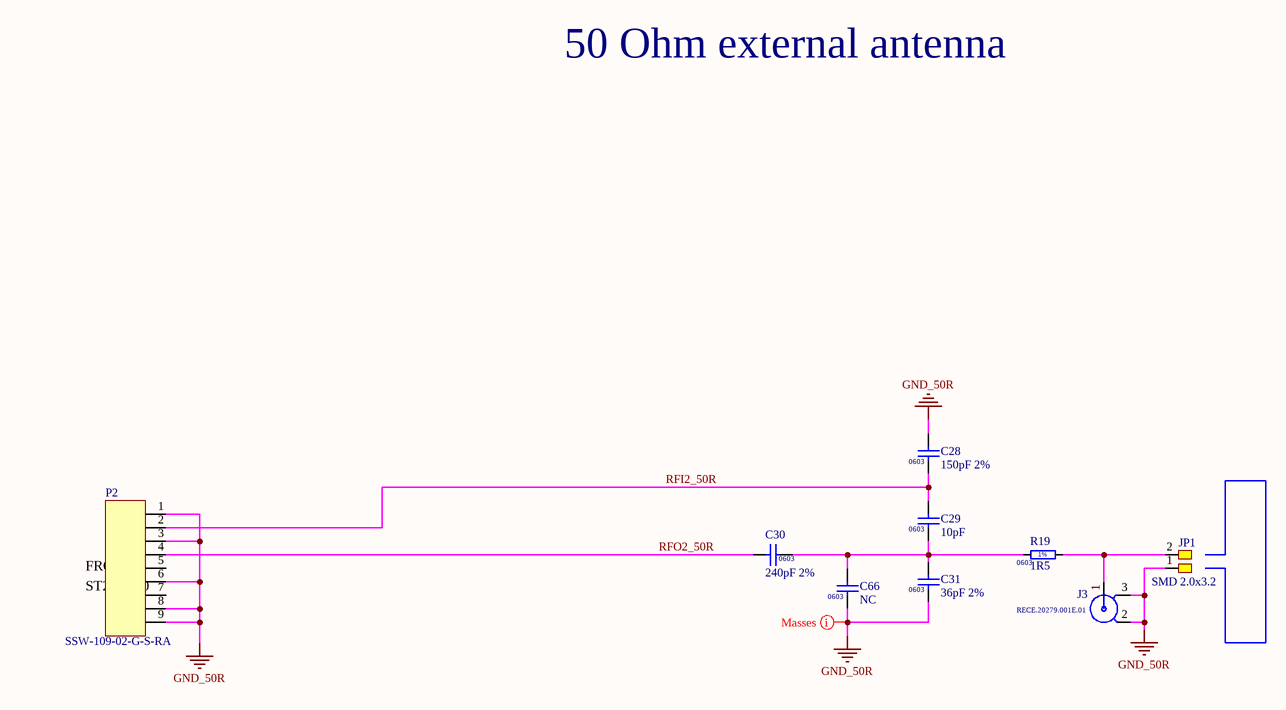
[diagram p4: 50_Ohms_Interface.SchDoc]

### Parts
C28  150pF 2%  [0603]
C29  10pF  [0603]
C30  240pF 2%  [0603]
C31  36pF 2%  [0603]
C66  NC  [0603]
J3  RECE.20279.001E.01  [TAOGLAS-RECE.20279.001E.01]
JP1  SMD 2.0x3.2  [PADS-x2-CMS-2.0x3.2-PAS-2.54]  (no BOM)
P2  SSW-109-02-G-S-RA  [SAMTEC-SSW-1X9PTS-RA-THROUGH-HOLE]
R19  1R5  [0603]

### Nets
GND_50R: C28.2 C31.1 C66.1 J3.2 J3.3 JP1.1 P2.1 P2.3 P2.6 P2.8 P2.9
RFI2_50R: C28.1 C29.2 P2.2
RFO2_50R: C30.1 P2.4
NetC29_1: C29.1 C30.2 C31.2 C66.2 R19.1
NetJ3_1: J3.1 JP1.2 R19.2

Not connected (* = marked no-connect by the designer): P2 5 7

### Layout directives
net class Masses: GND_50R

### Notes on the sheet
- 50 Ohm external antenna
- FROM
- ST25R200

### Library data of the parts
C28 = Capacitor 0603 150pF 50V 2% COG: as C13 on sheet Hub_And_C7_Antennas
C29 = Capacitor 0603 10pF 25V 5% C0G: as C14 on sheet Hub_And_C7_Antennas
C30 = Capacitor 0603 240pF 50V 2% COG: Manufacturer: MULTI-SOURCES; PickPlace: Yes
C31 = Capacitor 0603 36pF 50V 2% COG: Manufacturer: MULTI-SOURCES; PickPlace: Yes
C66 = Capacitor 0603 NC: Capacitor 0603 NOT FITTED; Manufacturer: MULTI-SOURCES; NOT-FITTED: X; PickPlace: Yes
J3 = RECE.20279.001E.01: CONN RECE.20279.001E.01; Manufacturer: TAOGLASS; PickPlace: Yes
JP1 = PADS-x2-CMS-2.0x3.2-PAS-2.54: 2 SMD PADS 2.0x3.2; NOT-FITTED: X; PickPlace: No
P2 = SSW-109-02-G-S-RA: as P4 on sheet C6_Antenna_Module
R19 = Resistor 0603 1R5 1%: as R16 on sheet Hub_And_C7_Antennas

## Sheet Flex_Antenna.SchDoc: STEVAL-25R200
size A3; Organization: STMicroelectronics; Address1: SMD Division; Address2: 190, avenue Célestin COQ; Address3: 13106 ROUSSET Cedex; Address4: FRANCE; Revision: A2; SheetNumber: 5; SheetTotal: 7; PageSetup: Record=PageOptions¦CenterHorizontal=True¦CenterVertical=True¦PrintScale=0.71¦XCorrection=1.00¦YCorrection=1.00¦PrintKind=0¦BorderSize=5000000¦LeftOffset=0¦BottomOffset=0¦Orientation=2¦PaperLength=1000¦PaperWidth=1000¦Scale=100¦PaperSource=7¦PrintQuality=-4¦MediaType=1¦DitherType=10¦PaperKind=A4¦PrintScaleMode=1; Reference: /
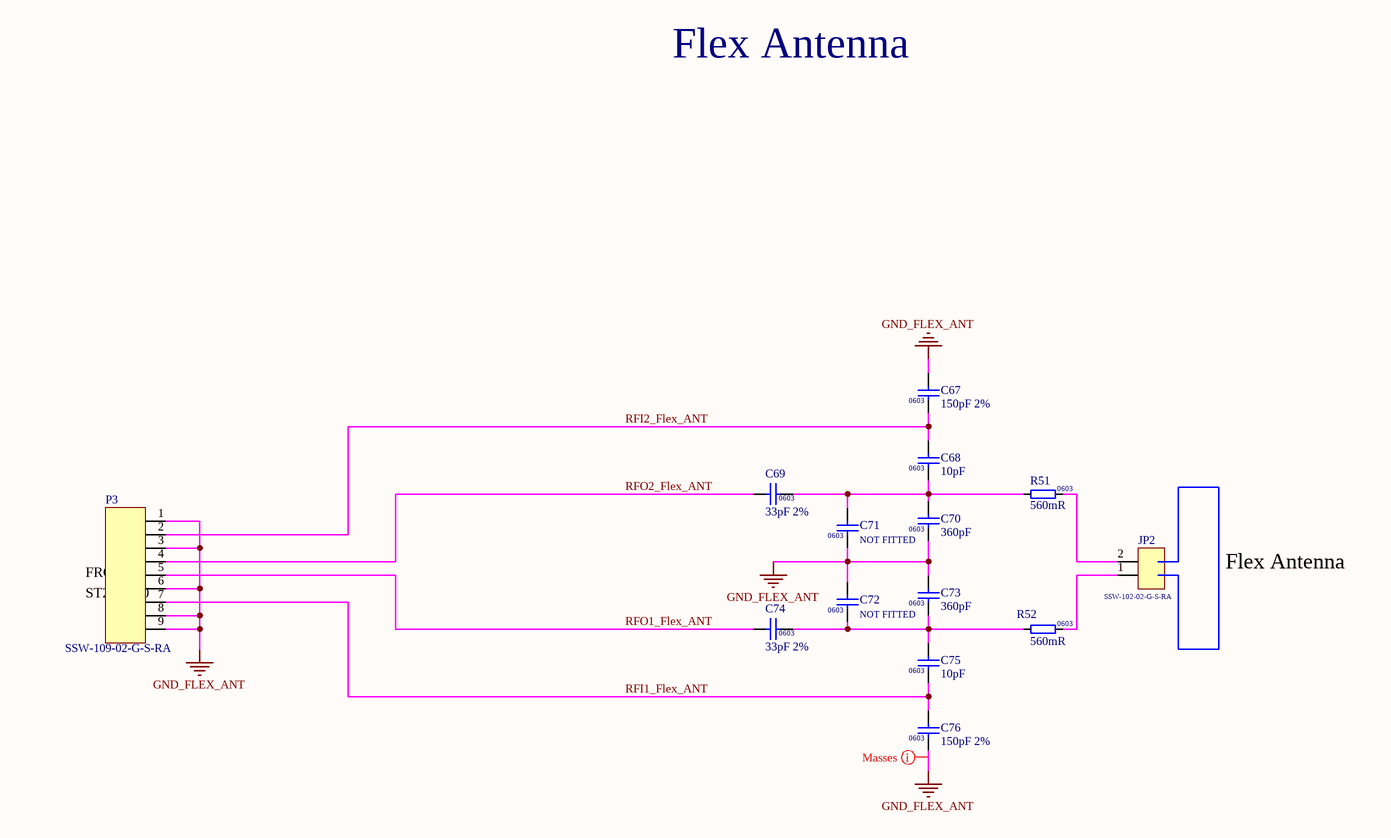
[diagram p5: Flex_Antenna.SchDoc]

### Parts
C67  150pF 2%  [0603]
C68  10pF  [0603]
C69  33pF 2%  [0603]
C70  360pF  [0603]
C71  NOT FITTED  [0603]
C72  NOT FITTED  [0603]
C73  360pF  [0603]
C74  33pF 2%  [0603]
C75  10pF  [0603]
C76  150pF 2%  [0603]
JP2  SSW-102-02-G-S-RA  [SAMTEC-SSW-1X2PTS-RA-THROUGH-HOLE]
P3  SSW-109-02-G-S-RA  [SAMTEC-SSW-1X9PTS-RA-THROUGH-HOLE]
R51  560mR  [0603]
R52  560mR  [0603]

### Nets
GND_FLEX_ANT: C67.2 C70.1 C71.1 C72.2 C73.2 C76.1 P3.1 P3.3 P3.6 P3.8 P3.9
RFI1_Flex_ANT: C75.1 C76.2 P3.7
RFI2_Flex_ANT: C67.1 C68.2 P3.2
RFO1_Flex_ANT: C74.1 P3.5
RFO2_Flex_ANT: C69.1 P3.4
NetC68_1: C68.1 C69.2 C70.2 C71.2 R51.1
NetC72_1: C72.1 C73.1 C74.2 C75.2 R52.1
NetJP2_1: JP2.1 R52.2
NetJP2_2: JP2.2 R51.2

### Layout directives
net class Masses: GND_FLEX_ANT

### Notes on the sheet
- Flex Antenna
- FROM
- ST25R200

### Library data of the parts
C67 C76 = Capacitor 0603 150pF 50V 2% COG: as C13 on sheet Hub_And_C7_Antennas
C68 C75 = Capacitor 0603 10pF 25V 5% C0G: as C14 on sheet Hub_And_C7_Antennas
C69 C74 = Capacitor 0603 39pF 50V 2% COG: Capacitor 0603 33pF 50V 2% COG; Manufacturer: MURATA; Manufacturer Part Number: GCM1885C1H330GA16D; PickPlace: Yes
C70 = Capacitor 0603 330pF 25V C0G 2%: Capacitor 0603 330pF 50V C0G 2%; Manufacturer: MURATA; Manufacturer Part Number: GRM1885C1H361GA01D; PickPlace: Yes
C71 C72 = Capacitor 0603 10pF 25V 5% C0G: PickPlace: Yes
C73 = Capacitor 0603 330pF 25V C0G 2%: Capacitor 0603 360pF 50V C0G 2%; Manufacturer: MURATA; Manufacturer Part Number: GRM1885C1H361GA01D; PickPlace: Yes
JP2 = SSW-102-02-G-S-RA: CONNECTOR SSW-102-02-G-S-RA; Manufacturer: SAMTEC; PickPlace: No
P3 = SSW-109-02-G-S-RA: as P4 on sheet C6_Antenna_Module
R51 R52 = Resistor 0603 560MilliOhm 1%: Manufacturer: MULTI-SOURCES; PickPlace: Yes

## Sheet Tags.SchDoc: STEVAL-25R200
size A3; Organization: STMicroelectronics; Address1: SMD Division; Address2: 190, avenue Célestin COQ; Address3: 13106 ROUSSET Cedex; Address4: FRANCE; Revision: A2; SheetNumber: 7; SheetTotal: 7; PageSetup: Record=PageOptions¦CenterHorizontal=True¦CenterVertical=True¦PrintScale=0.71¦XCorrection=1.00¦YCorrection=1.00¦PrintKind=0¦BorderSize=5000000¦LeftOffset=0¦BottomOffset=0¦Orientation=2¦PaperLength=1000¦PaperWidth=1000¦Scale=100¦PaperSource=7¦PrintQuality=-4¦MediaType=1¦DitherType=10¦PaperKind=A4¦PrintScaleMode=1; Reference: /
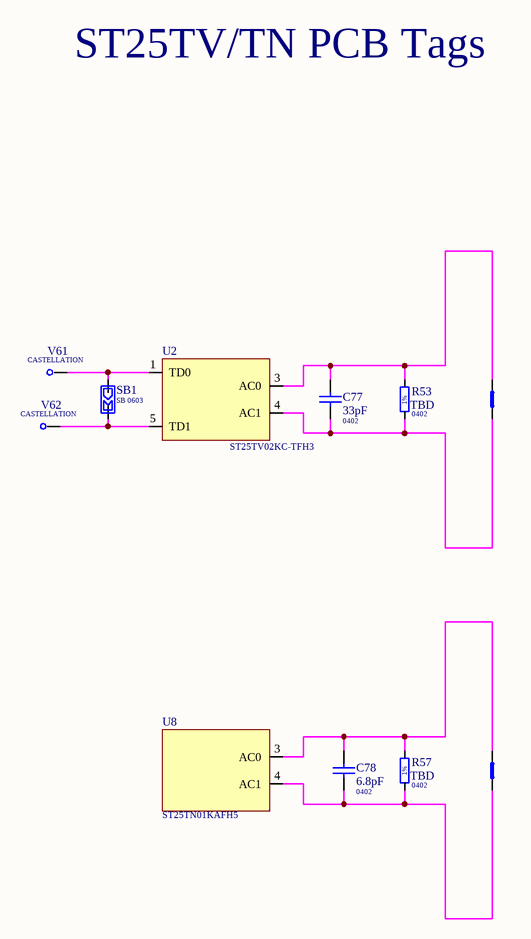
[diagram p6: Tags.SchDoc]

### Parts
C77  33pF  [0402]
C78  6.8pF  [0402]
NT_TAG1  Net-Tie-Width-0.10mm  [Net-Tie-WIDTH-0.10mm]  (value not drawn)  (net tie, no BOM)
NT_TAG2  Net-Tie-Width-0.10mm  [Net-Tie-WIDTH-0.10mm]  (value not drawn)  (net tie, no BOM)
R53  TBD  [0402]
R57  TBD  [0402]
SB1  SB 0603  [STRAP-FORMAT-0603-OUVERT]
U2  ST25TV02KC-TFH3  [ST-UFDFPN5-Pas=0.4-PKG-1.7x1.4]
U8  ST25TN01KAFH5  [ST-UFDFPN5-Pas=0.4-PKG-1.7x1.4]
V61  CASTELLATION  [CASTELLATED_VIA]  (no BOM)
V62  CASTELLATION  [CASTELLATED_VIA]  (no BOM)

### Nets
NetC77_1: C77.1 NT_TAG1.1 R53.1 U2.4(AC1)
NetC77_2: C77.2 NT_TAG1.2 R53.2 U2.3(AC0)
NetC78_1: C78.1 NT_TAG2.1 R57.1 U8.4(AC1)
NetC78_2: C78.2 NT_TAG2.2 R57.2 U8.3(AC0)
NetSB1_1: SB1.1 U2.5(TD1) V62.1
NetSB1_2: SB1.2 U2.1(TD0) V61.1

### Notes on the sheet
- ST25TV/TN PCB Tags

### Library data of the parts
C77 = Capacitor 0402 33pF 50V 5% COG: Manufacturer: MULTI-SOURCES; PickPlace: Yes
C78 = Capacitor 0402 6.8pF 50V 5% COG: Manufacturer: MULTI-SOURCES; PickPlace: Yes
NT_TAG1 NT_TAG2 = Net-Tie-Width-0.10mm: Net Tie Width 0.10mm; PickPlace: No
R53 R57 = Resistor 0402 TBD: RESISTOR 0402 TO BE DEFINED (NOT FITTED); NOT-FITTED: X; PickPlace: Yes
SB1 = STRAP-0603-OUVERT: SOLDER BRIDGE OPEN SIZE 0603; NOT-FITTED: X; PickPlace: No
U2 = ST25TV02KC-TFH3: NFC TAG IC ST25TV02KC-TFH3 UFDFPN5; Manufacturer: ST MICRO; PickPlace: Yes
U8 = ST25TN01KAFH5: NFC TAG IC ST25TN01KAFH5 UFDFPN5; Manufacturer: ST MICRO; PickPlace: Yes
V61 V62 = CASTELLATED_VIA: NOT-FITTED: X; PickPlace: No

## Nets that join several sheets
5V_USB_CHGR: ST25R200_Module (6 pins), STLink_V2 (9 pins)
GND: ST25R200_Module (60 pins), STLink_V2 (34 pins)
VCC_STLK: ST25R200_Module (J6.3 V46.1), STLink_V2 (23 pins)
N_RST_G0: ST25R200_Module (U7.6 V8.1), STLink_V2 (C7.2 R54.1 SW1.1 V40.1)
T_JTCK: ST25R200_Module (J6.6 U7.25 V4.1), STLink_V2 (U1.15 U1.26 V39.1)
T_SWDIO_IN: ST25R200_Module (J6.4 U7.24 V3.1), STLink_V2 (R55.1 U1.25 V42.1)
UART_RX: ST25R200_Module (U7.10 V7.1), STLink_V2 (U1.12 V43.1)
UART_TX: ST25R200_Module (D6.K J6.14 U7.9 V6.1), STLink_V2 (U1.13 V44.1)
